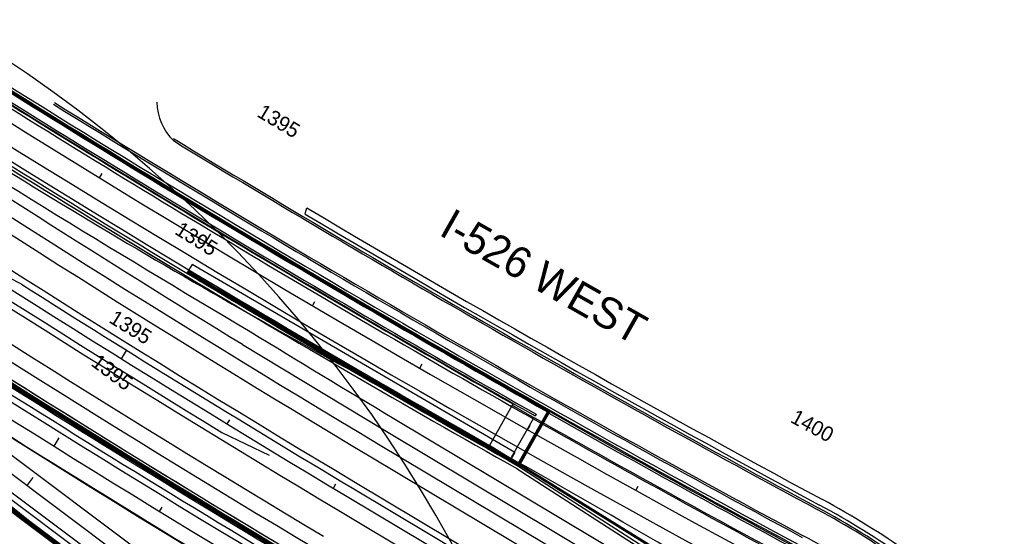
# Model space of a CAD drawing. Extents: x 2338610 to 2351914, y 366540 to 376484.
# Drawn here: x 2346018 to 2346817, y 369854 to 370269 of the extents above; entities that cross this region are included whole.
import ezdxf

# ---------------------------------------------------------------- set-up
doc = ezdxf.new("R2010")
doc.units = 0
for name, color, linetype in [('RD_HC_Cl', 7, 'Continuous'), ('RD_HC_CL_Rel', 7, 'Continuous'), ('RD_PD_Bridge', 7, 'Continuous'), ('RD_PD_Final_LnLine', 7, 'Continuous'), ('RD_PD_Final_TrvlWay', 7, 'Continuous'), ('RD_PD_FOC', 7, 'Continuous'), ('RD_PD_MedBWall', 7, 'Continuous'), ('RD_PD_MedGR', 7, 'Continuous'), ('RD_PD_NOISE-WALL-GM', 7, 'Continuous'), ('RD_PD_PaveShd', 7, 'Continuous'), ('RD_PD_SW', 7, 'Continuous'), ('RD_PD_WallFill', 7, 'Continuous'), ('TR SN UNASSIGNED 4', 7, 'Continuous'), ('TR SN UNASSIGNED 7', 7, 'Continuous')]:
    doc.layers.add(name, color=color, linetype=linetype)

msp = doc.modelspace()

# ---------------------------------------------------------------- linework, layer by layer
at = {"layer": 'RD_HC_Cl'}
for p, q in [((2345614.6, 370194.71), (2346103.37, 369803.49)), ((2345614.6, 370194.71), (2346103.37, 369803.49)), ((2345614.6, 370194.71), (2346103.37, 369803.49)), ((2345614.6, 370194.71), (2346103.37, 369803.49)), ((2345717.08, 370123.86), (2346548.69, 369501.55)), ((2346281.57, 369885.43), (2351112.4, 367003.22))]:
    msp.add_line(p, q, dxfattribs=at)
for centre, radius, start, end in [((2352034, 379865.62), 11400.7, 232.99132, 241.72492), ((2352152.85, 379726.19), 11459.16, 233.263715, 239.178507), ((2349158.41, 375253.94), 6000, 236.195282, 241.602511), ((2349158.41, 375253.94), 6000, 236.195282, 241.602511), ((2349158.41, 375253.94), 6000, 236.195282, 241.602511), ((2349158.41, 375253.94), 6000, 236.195282, 241.602511), ((2345401.07, 369318.89), 1100, 337.175, 58.13524), ((2345401.07, 369318.89), 1100, 337.175, 58.13524), ((2345401.07, 369318.89), 1100, 337.175, 58.13524), ((2345401.07, 369318.89), 1100, 337.175, 58.13524), ((2342405.09, 362762.64), 8200, 59.178507, 61.602511), ((2342405.09, 362762.64), 8200, 59.178507, 61.602511), ((2342405.09, 362762.64), 8200, 59.178507, 61.602511), ((2342405.09, 362762.64), 8200, 59.178507, 61.602511)]:
    msp.add_arc(centre, radius, start, end, dxfattribs=at)
at = {"layer": 'RD_HC_CL_Rel'}
msp.add_arc((2352152.85, 379726.19), 11547.58, 233.263715, 239.178507, dxfattribs=at)
at = {"layer": 'RD_PD_Bridge'}
for p, q in [((2346414.48, 369958.88), (2346396.22, 369926.56)), ((2346431.33, 369948.05), (2346413.63, 369916.7)), ((2346645.94, 369770.43), (2346395.73, 369925.69)), ((2346646.53, 369771.39), (2346396.22, 369926.56))]:
    msp.add_line(p, q, dxfattribs=at)
for radius, start in [(11390.7, 240.436294), (11389.58, 240.436284)]:
    msp.add_arc((2352034, 379865.62), radius, start, 241.724919, dxfattribs=at)
at = {"layer": 'RD_PD_Final_LnLine'}
for p, q in [((2345717.08, 370123.86), (2346548.69, 369501.55)), ((2346197.13, 370007.86), (2346312.91, 369937.96)), ((2346312.91, 369937.96), (2346990.8, 369533.51)), ((2346306.76, 369927.65), (2346984.82, 369523.11)), ((2346300.62, 369917.35), (2346978.67, 369512.8))]:
    msp.add_line(p, q, dxfattribs=at)
for centre, radius, start, end in [((2351872.76, 379241.01), 11000, 231.263715, 239.178507), ((2351872.76, 379241.01), 11000, 231.263715, 239.178507), ((2351872.76, 379241.01), 11000, 231.263715, 239.178507), ((2351872.76, 379241.01), 11000, 231.263715, 239.178507), ((2352152.85, 379726.19), 11409.99, 233.263715, 239.178507), ((2352152.85, 379726.19), 11421.99, 233.263715, 239.178507), ((2352152.85, 379726.19), 11496.33, 233.317765, 239.178507), ((2352152.85, 379726.19), 11547.58, 233.263715, 239.178507), ((2352152.85, 379726.19), 11397.99, 234.598626, 238.498636), ((2352034, 379865.62), 11368.2, 238.213816, 241.724919), ((2346172.42, 370203.3), 44.1, 180.72554, 225.54422), ((2352034, 379865.62), 11344.2, 238.706281, 241.724919), ((2346341.62, 369282.71), 672.5, 54.83658, 61.72492), ((2346341.62, 369282.71), 648.5, 54.83658, 61.72492)]:
    msp.add_arc(centre, radius, start, end, dxfattribs=at)
at = {"layer": 'RD_PD_Final_TrvlWay'}
for p, q in [((2345710.14, 370114.06), (2346541.5, 369491.94)), ((2345882.78, 370014.85), (2346297.71, 369704.35)), ((2346319.06, 369948.26), (2346996.78, 369543.91))]:
    msp.add_line(p, q, dxfattribs=at)
for centre, radius, start, end in [((2352034, 379865.62), 11400.7, 232.99132, 241.724919), ((2352034, 379865.62), 11416.7, 232.99132, 241.724919), ((2352152.85, 379726.19), 11508.33, 233.263715, 239.178507), ((2352152.85, 379726.19), 11535.58, 233.263715, 239.178507), ((2352001.85, 379817.31), 11386.16, 235.48365, 239.386127), ((2352152.85, 379726.19), 11559.58, 237.151929, 239.178507), ((2352152.85, 379726.19), 11385.99, 238.498636, 239.178507)]:
    msp.add_arc(centre, radius, start, end, dxfattribs=at)
at = {"layer": 'RD_PD_FOC'}
for centre, radius, start, end in [((2352034, 379865.62), 11369.7, 238.213816, 241.724919), ((2352034, 379865.62), 11342.7, 238.702787, 241.724919), ((2346341.62, 369282.71), 674, 54.83658, 61.72492)]:
    msp.add_arc(centre, radius, start, end, dxfattribs=at)
at = {"layer": 'RD_PD_MedBWall'}
for p, q in [((2346276.58, 369683.94), (2345707.25, 370109.98)), ((2345703.78, 370105.09), (2346289, 369667.15)), ((2345703.78, 370105.09), (2346272.99, 369679.13)), ((2345704.35, 370105.9), (2346273.59, 369679.93)), ((2346289.6, 369667.95), (2345704.35, 370105.9)), ((2346156.61, 370072.18), (2346154.09, 370067.85)), ((2346416.57, 369920.78), (2346156.61, 370072.18)), ((2346154.1, 370067.85), (2346153.59, 370066.99)), ((2346415.08, 369959.93), (2346413.93, 369957.9)), ((2346414.05, 369916.46), (2346413.46, 369915.41)), ((2346416.57, 369920.78), (2346414.05, 369916.46)), ((2346419.82, 369909.65), (2346575.38, 369809.69)), ((2346418.56, 369907.69), (2346574.12, 369807.73))]:
    msp.add_line(p, q, dxfattribs=at)
for centre, radius, start, end in [((2352001.98, 379817.23), 11371.83, 235.499002, 239.043799), ((2352001.98, 379817.23), 11374.16, 235.499002, 239.043799), ((2352034, 379865.62), 11376.2, 237.52318, 241.724919), ((2352034, 379865.62), 11378.2, 237.52318, 241.724919), ((2352034, 379865.62), 11390.7, 237.52318, 240.436294), ((2352034, 379865.62), 11388.37, 237.52318, 240.436294), ((2352152.85, 379726.19), 11525.58, 235.613637, 239.178507), ((2352152.85, 379726.19), 11524.58, 235.613637, 239.178507), ((2352152.85, 379726.19), 11522.33, 235.613637, 239.178507), ((2352152.85, 379726.19), 11520.33, 235.613637, 239.178507), ((2352152.85, 379726.19), 11530.58, 235.613637, 239.178507), ((2352034, 379865.62), 11432.13, 239.030937, 240.581171), ((2352001.98, 379817.23), 11374.16, 239.043799, 239.389285), ((2352001.98, 379817.23), 11371.83, 239.043802, 239.389285), ((2352034, 379865.62), 11429.8, 239.030937, 240.581171), ((2352034, 379865.62), 11427.7, 239.030937, 240.436611), ((2352034, 379865.62), 11426.7, 239.030937, 240.436611), ((2352034, 379865.62), 11390.7, 240.429891, 240.436294)]:
    msp.add_arc(centre, radius, start, end, dxfattribs=at)
at = {"layer": 'RD_PD_MedGR'}
for p, q in [((2346019.31, 370056.19), (2345981.74, 370075.38)), ((2346180.67, 369936.96), (2346218.65, 369918.57)), ((2346285.67, 369892.3), (2346616, 369695.22))]:
    msp.add_line(p, q, dxfattribs=at)
for radius, start, end in [(11467.16, 233.263715, 238.613636), (11451.16, 237.613636, 239.178507)]:
    msp.add_arc((2352152.85, 379726.19), radius, start, end, dxfattribs=at)
at = {"layer": 'RD_PD_NOISE-WALL-GM'}
msp.add_line((2346433.75, 369951.65), (2346433.01, 369950.35), dxfattribs=at)
for radius, start, end in [(11387.87, 237.52318, 240.538561), (11386.37, 237.52318, 240.538561), (11380.7, 240.58136, 241.724919), (11379.2, 240.58136, 241.724919)]:
    msp.add_arc((2352034, 379865.62), radius, start, end, dxfattribs=at)
at = {"layer": 'RD_PD_PaveShd'}
for p, q in [((2345704.35, 370105.9), (2346273.59, 369679.93)), ((2346288.32, 369896.74), (2346673.05, 369667.19)), ((2346274.83, 369874.12), (2346659.56, 369644.58))]:
    msp.add_line(p, q, dxfattribs=at)
for centre, radius, start, end in [((2352034, 379865.62), 11426.7, 233.088517, 240.436611), ((2352152.85, 379726.19), 11445.99, 233.263715, 239.178507), ((2352152.85, 379726.19), 11472.33, 233.263715, 239.178507), ((2352152.85, 379726.19), 11520.33, 233.613638, 239.178507), ((2352001.98, 379817.23), 11374.16, 235.482859, 239.043799), ((2352034, 379865.62), 11432.13, 239.030937, 240.581171)]:
    msp.add_arc(centre, radius, start, end, dxfattribs=at)
at = {"layer": 'RD_PD_SW'}
for p, q in [((2346248.14, 370115.18), (2346249.03, 370117.75)), ((2346247.72, 370112.71), (2346248.14, 370115.18))]:
    msp.add_line(p, q, dxfattribs=at)
for centre, radius, start, end in [((2352034, 379865.62), 11335.2, 239.312559, 241.724919), ((2352034, 379865.62), 11340.2, 239.319887, 241.724919), ((2346341.62, 369282.71), 676.5, 54.83658, 61.72492), ((2346341.62, 369282.71), 681.5, 54.83658, 61.72492)]:
    msp.add_arc(centre, radius, start, end, dxfattribs=at)
at = {"layer": 'RD_PD_WallFill'}
for p, q in [((2345702.91, 370103.86), (2346294.91, 369660.86)), ((2346294.91, 369660.86), (2345702.91, 370103.86)), ((2346294.81, 369661.56), (2345703.2, 370104.27)), ((2346294.71, 369662.26), (2345703.49, 370104.68)), ((2345703.78, 370105.09), (2346294.61, 369662.95)), ((2345703.78, 370105.09), (2346294.61, 369662.95)), ((2345703.78, 370105.09), (2346294.61, 369662.95)), ((2346153.44, 370066.75), (2346152.67, 370065.46)), ((2346419.38, 369911.98), (2346442.88, 369953.59)), ((2346419.57, 369911.3), (2346443.56, 369953.78)), ((2346419.76, 369910.62), (2346444.25, 369953.96)), ((2346419.95, 369909.94), (2346444.93, 369954.15))]:
    msp.add_line(p, q, dxfattribs=at)
for centre, radius, start, end in [((2352034, 379865.62), 11380.2, 237.52318, 240.573804), ((2352034, 379865.62), 11379.7, 237.52318, 240.576323), ((2352034, 379865.62), 11379.2, 237.52318, 240.578842), ((2352034, 379865.62), 11378.7, 237.52318, 240.581362), ((2352152.85, 379726.19), 11524.58, 235.613637, 239.178507), ((2352152.85, 379726.19), 11524.08, 235.613637, 239.178507), ((2352152.85, 379726.19), 11523.58, 235.613637, 239.178507), ((2352152.85, 379726.19), 11523.08, 235.613637, 239.178507), ((2352034, 379865.62), 11429.49, 239.030937, 240.581171), ((2352034, 379865.62), 11428.99, 239.030937, 240.578667), ((2352034, 379865.62), 11428.49, 239.030937, 240.576162), ((2352034, 379865.62), 11427.99, 239.030937, 240.573656)]:
    msp.add_arc(centre, radius, start, end, dxfattribs=at)
at = {"layer": 'TR SN UNASSIGNED 7'}
for p, q in [((2346082.09, 370141.9), (2346084.18, 370145.31)), ((2346167.61, 370090.07), (2346171.72, 370096.93)), ((2346253.58, 370038.99), (2346255.6, 370042.43)), ((2346099.7, 369996.24), (2346103.93, 370003.04)), ((2346339.99, 369988.66), (2346341.99, 369992.13)), ((2346184.84, 369943.79), (2346186.92, 369947.21)), ((2346426.84, 369939.1), (2346428.81, 369942.58)), ((2346045.41, 369925.89), (2346049.64, 369932.68)), ((2346023.75, 369894.37), (2346028.54, 369900.78)), ((2346270.43, 369892.08), (2346272.49, 369895.52)), ((2346514.13, 369890.3), (2346516.06, 369893.8)), ((2346130.51, 369873.37), (2346132.6, 369876.78))]:
    msp.add_line(p, q, dxfattribs=at)

# ---------------------------------------------------------------- texts
at = {"layer": 'TR SN UNASSIGNED 4'}
msp.add_text('I-526 WEST', height=25, rotation=330.50912, dxfattribs=at).set_placement((2346354.55, 370096.41))
at = {"layer": 'TR SN UNASSIGNED 7'}
for s, rotation, p in [('1395', 329.03167, (2346208.14, 370191.69)), ('1395', 328.11364, (2346141.86, 370097.21)), ('1395', 328.06931, (2346088.85, 370026.07)), ('1395', 323.19179, (2346074.41, 369991.35)), ('1400', 331.54449, (2346637.76, 369945.64))]:
    msp.add_text(s, height=12, rotation=rotation, dxfattribs=at).set_placement(p)

doc.saveas('drawing.dxf')
